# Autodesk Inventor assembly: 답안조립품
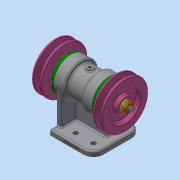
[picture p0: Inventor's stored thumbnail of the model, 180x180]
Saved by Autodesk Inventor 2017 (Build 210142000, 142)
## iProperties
Part Number: 답안조립품
Material: 일반
Document SubType Name: Assembly
Designer: 222
Author: 222
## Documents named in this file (12)
- C:\Users\222\Desktop\700606V1035\답안조립품.iam
- C:\Users\222\Desktop\700606V1035\본체.ipt
- C:\Users\222\Desktop\700606V1035\Ű 5x5x12.ipt
- C:\Users\222\Desktop\700606V1035\V-벨트풀리.ipt
- C:\Users\222\Desktop\700606V1035\너트 M10.ipt
- C:\Users\222\Desktop\700606V1035\베어링 6204.ipt
- C:\Users\222\Desktop\700606V1035\볼트 M4.ipt
- C:\Users\222\Desktop\700606V1035\스프링 와셔 10.ipt
- C:\Users\222\Desktop\700606V1035\오일 실 20 32 5.ipt
- C:\Users\222\Desktop\700606V1035\축.ipt
- C:\Users\222\Desktop\700606V1035\커버.ipt
- C:\Users\222\Desktop\700606V1035\평면 와셔 10x21.ipt
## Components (4 placed, 2 different names)
1. Ű 5x5x12:1
2. V-벨트풀리:1
3. V-벨트풀리:2
4. Ű 5x5x12:2
